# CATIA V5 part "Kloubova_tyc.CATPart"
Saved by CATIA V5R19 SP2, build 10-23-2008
Part number: Kloubove tyce
Bounding box of the stored display mesh (mm): x -30 to 60, y -69.776 to 69.776, z -69.736 to 469.736
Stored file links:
  D:\Catia fórum\Modely - Otazky\Naklapeni_oprava\Kloubova_tyc.CATPart
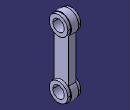
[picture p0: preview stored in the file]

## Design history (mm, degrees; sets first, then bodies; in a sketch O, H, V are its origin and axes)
Body1 (main body)
  Sketch1 on yz-plane, origin (0, 0, 0), H (0, 1, 0), V (0, 0, 1)
    circle A1 centre (0, 0) radius 40
    arc A2 centre (0, 0) radius 70 from (-50, 48.9898) to (50, 48.9898) ccw
    construction line L1 (-129.8975, 200) -> (180.7736, 200)
    point P3 (0, 400)
    arc A3 centre (0, 400) radius 70 from (-50, 351.0102) to (50, 351.0102) cw
    circle A4 centre (0, 400) radius 40
    line L2 (-50, 351.0102) -> (-50, 48.9898)
    construction line L3 (0, 400) -> (0, 103.5528)
    line L4 (50, 351.0102) -> (50, 48.9898)
    radius A1 = 40
    radius A2 = 70
    distance P3 L1 = 200
    distance P3 L2 = 50
    horizontal: L1 H
    symmetry: A2 A3 L1, A1 A4 L1, L2 L4 L3
    vertical: L2 V, L3 V
  Pad1: profile Sketch1, direction (1, 0, 0), length 40
  Sketch2 on end face of Pad1, origin (40, 0, 0), H (0, 1, 0), V (0, 0, 1)
    circle A1 centre (0, 0) radius 40
    reference projected circle E1 centre (0, 0) radius 40 from edge [end face of Pad1 | face of Pad1 from Sketch1.A1]
    circle A2 centre (0, 0) radius 65
    radius A2 = 65
    coincidence: A1 E1
  Pad2: profile Sketch2, direction (1, 0, 0), length 20
  RectPattern1: of Pad2, direction 1 instances 2, spacing 400, along edge [face of Pad1 from Sketch1.L4 | end face of Pad1]
  Plane1: type Offset, RefPlane end face of Pad1, Offset 25
  Mirror1: of the body so far, about Plane1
